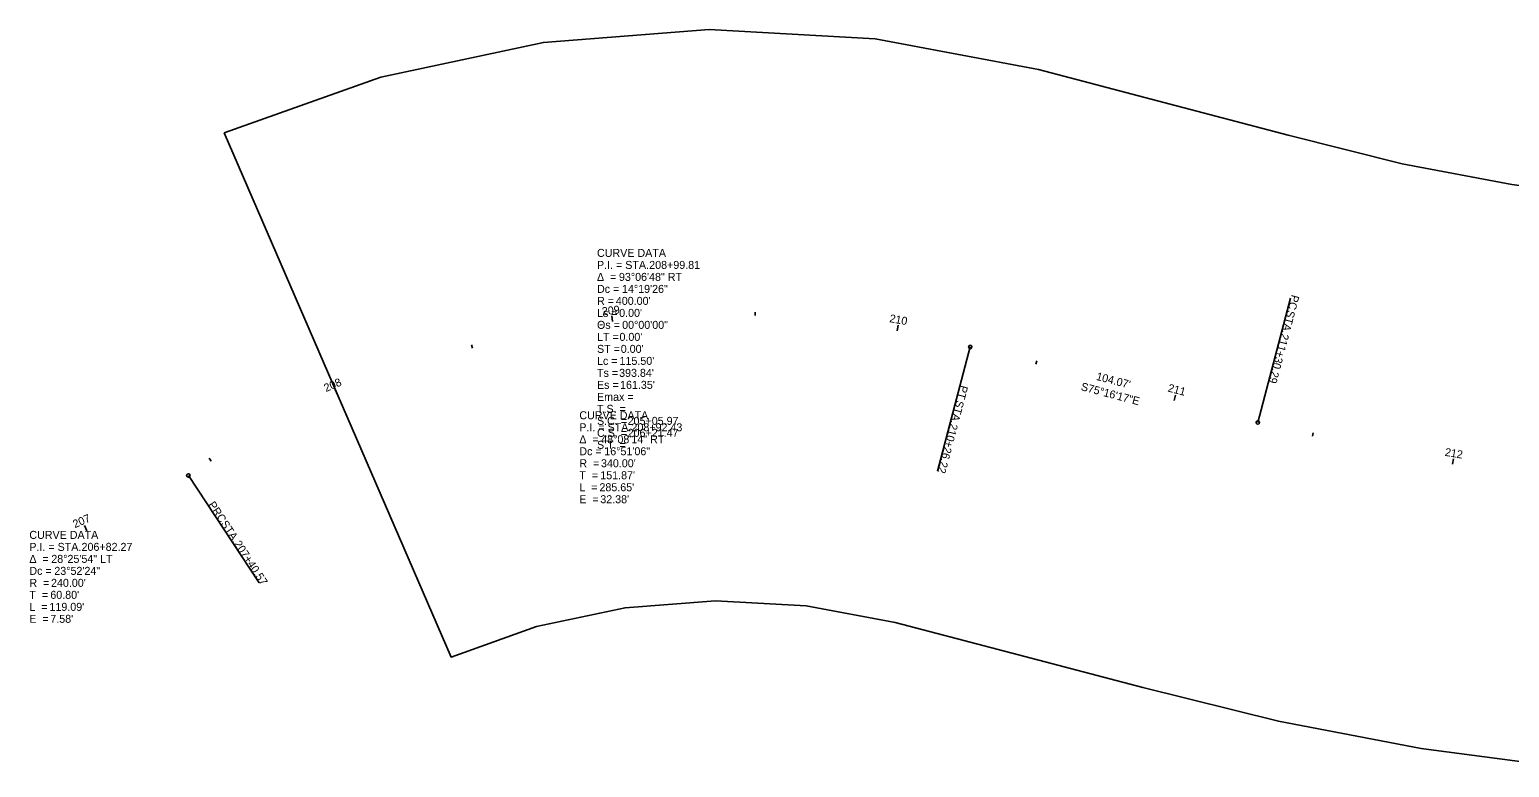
# Model space of a CAD drawing. Extents: x 1600023 to 1602105, y 286460 to 286887.
# Drawn here: x 1601069 to 1601587, y 286628 to 286887 of the extents above; entities that cross this region are included whole.
import ezdxf

# ---------------------------------------------------------------- set-up
doc = ezdxf.new("R2010")
doc.units = 0
for name, color, linetype in [('DT_X_Contour_Minor', 7, 'Continuous'), ('DT_X_Island', 7, 'Continuous'), ('DT_X_Terrain_Boundary', 7, 'Continuous'), ('DT_X_Void', 7, 'Continuous'), ('SC_Scratch3', 7, 'Continuous'), ('UT_X_Overhead_Electric', 7, 'Continuous')]:
    doc.layers.add(name, color=color, linetype=linetype)

msp = doc.modelspace()

# ---------------------------------------------------------------- linework, layer by layer
at = {"layer": 'DT_X_Island'}
for p, q in [((1601498.97, 286749.25), (1601510.41, 286792.77)), ((1601398.32, 286775.71), (1601386.88, 286732.19)), ((1601124.67, 286730.7), (1601149.45, 286693.13))]:
    msp.add_line(p, q, dxfattribs=at)
for centre in [(1601398.32, 286775.71), (1601498.97, 286749.25), (1601124.67, 286730.7)]:
    msp.add_circle(centre, 0.6, dxfattribs=at)
at = {"layer": 'SC_Scratch3'}
for p, q in [((1601273.15, 286784.67), (1601272.92, 286786.65)), ((1601323.06, 286786.69), (1601323.1, 286787.89)), ((1601372.73, 286781.39), (1601373.09, 286783.36)), ((1601224.07, 286775.34), (1601223.76, 286776.5)), ((1601421.32, 286769.66), (1601421.63, 286770.82)), ((1601176.89, 286758.93), (1601176.09, 286760.77)), ((1601469.68, 286756.95), (1601470.19, 286758.88)), ((1601518.1, 286744.48), (1601518.37, 286745.65)), ((1601132.62, 286735.78), (1601131.99, 286736.8)), ((1601567.11, 286734.62), (1601567.44, 286736.6)), ((1601089.09, 286711.32), (1601088.28, 286713.15))]:
    msp.add_line(p, q, dxfattribs=at)
at = {"layer": 'UT_X_Overhead_Electric'}
msp.add_lwpolyline([(1601137.18, 286850.71), (1601216.59, 286667.15), (1601246.49, 286677.8), (1601277.54, 286684.41), (1601309.18, 286686.86), (1601340.88, 286685.12), (1601372.06, 286679.21), (1601415.24, 286667.86), (1601458.76, 286656.42), (1601506.2, 286644.63), (1601556.18, 286635.08), (1601606.63, 286628.49), (1601626.67, 286827.49), (1601587.9, 286832.55), (1601549.49, 286839.88), (1601509.61, 286849.85), (1601466.08, 286861.29), (1601422.21, 286872.82), (1601365.04, 286883.66), (1601306.93, 286886.85), (1601248.92, 286882.35), (1601192, 286870.23)], close=True, dxfattribs=at)

# ---------------------------------------------------------------- texts
at = {"layer": 'DT_X_Contour_Minor'}
msp.add_text("104.07'", height=2.8, rotation=345.2715, dxfattribs=at).set_placement((1601442.2, 286764.22))
at = {"layer": 'DT_X_Island'}
for s, rotation, p in [('PC', 255.2715, (1601510.83, 286794.17)), (' STA. ', 255.2715, (1601509.66, 286789.74)), ('211+30.29', 255.2715, (1601507.26, 286780.6)), ('PT', 255.2715, (1601394.89, 286762.48)), (' STA. ', 255.2715, (1601393.77, 286758.21)), ('210+26.22', 255.2715, (1601391.36, 286749.07)), ('PRC', 303.4087, (1601131.46, 286720.49)), (' STA. ', 303.4087, (1601135.28, 286714.69)), ('207+40.57', 303.4087, (1601140.49, 286706.8))]:
    msp.add_text(s, height=2.8, rotation=rotation, dxfattribs=at).set_placement(p)
at = {"layer": 'DT_X_Terrain_Boundary'}
for s, p in [('CURVE DATA', (1601267.69, 286807.25)), ('P.I. = STA. ', (1601267.69, 286803.05)), ('208+99.81', (1601285.96, 286803.05)), ('Δ  = ', (1601267.69, 286798.85)), ('93°06\'48" RT', (1601275.37, 286798.85)), ('Dc = ', (1601267.69, 286794.65)), ('14°19\'26"', (1601276.43, 286794.65)), ('R = ', (1601267.69, 286790.45)), ("400.00'", (1601274.28, 286790.45)), ('Θs = ', (1601267.69, 286782.05)), ('Ls = ', (1601267.69, 286786.25)), ("0.00'", (1601275.45, 286786.25)), ('00°00\'00"', (1601276.49, 286782.05)), ('LT = ', (1601267.69, 286777.85)), ("0.00'", (1601275.55, 286777.85)), ('ST = ', (1601267.69, 286773.65)), ("0.00'", (1601276, 286773.65)), ('Lc = ', (1601267.69, 286769.45)), ("115.50'", (1601275.57, 286769.45)), ('Ts = ', (1601267.69, 286765.25)), ('Es = ', (1601267.69, 286761.05)), ("393.84'", (1601275.43, 286765.25)), ("161.35'", (1601275.75, 286761.05)), ('Emax = ', (1601267.69, 286756.85)), ('T.S. = ', (1601267.69, 286752.65)), ('CURVE DATA', (1601261.5, 286750.4)), ('P.I. = STA. ', (1601261.5, 286746.2)), ('S.C. = ', (1601267.69, 286748.45)), ('205+05.97', (1601278.41, 286748.45)), ('208+92.43', (1601279.76, 286746.2)), ('Δ  = ', (1601261.5, 286742)), ('C.S. = ', (1601267.69, 286744.25)), ('48°08\'14" RT', (1601269.17, 286742)), ('206+21.47', (1601278.41, 286744.25)), ('Dc = ', (1601261.5, 286737.8)), ('S.T. = ', (1601267.69, 286740.05)), ('16°51\'06"', (1601270.24, 286737.8)), ('R  = ', (1601261.5, 286733.6)), ("340.00'", (1601269.08, 286733.6)), ('T  = ', (1601261.5, 286729.4)), ('L  = ', (1601261.5, 286725.2)), ("285.65'", (1601268.54, 286725.2)), ("151.87'", (1601268.84, 286729.4)), ('E  = ', (1601261.5, 286721)), ("32.38'", (1601268.84, 286721)), ('CURVE DATA', (1601069.01, 286708.52)), ('P.I. = STA. ', (1601069.01, 286704.32)), ('206+82.27', (1601087.28, 286704.32)), ('Δ  = ', (1601069.01, 286700.12)), ('28°25\'54" LT', (1601076.69, 286700.12)), ('Dc = ', (1601069.01, 286695.92)), ('23°52\'24"', (1601077.75, 286695.92)), ('R  = ', (1601069.01, 286691.72)), ("240.00'", (1601076.59, 286691.72)), ('T  = ', (1601069.01, 286687.52)), ('L  = ', (1601069.01, 286683.32)), ("119.09'", (1601076.05, 286683.32)), ("60.80'", (1601076.35, 286687.52)), ('E  = ', (1601069.01, 286679.12)), ("7.58'", (1601076.35, 286679.12))]:
    msp.add_text(s, height=2.8, dxfattribs=at).set_placement(p)
at = {"layer": 'DT_X_Void'}
msp.add_text('S75°16\'17"E', height=2.8, rotation=345.2715, dxfattribs=at).set_placement((1601436.85, 286760.62))
at = {"layer": 'SC_Scratch3'}
for s, rotation, p in [('209', 6.5413, (1601269.57, 286786.77)), ('210', 349.6896, (1601369.89, 286784.45)), ('208', 23.393, (1601172.83, 286759.9)), ('211', 345.2715, (1601467.27, 286760.17)), ('212', 350.4996, (1601564.29, 286737.63)), ('207', 23.7245, (1601084.96, 286712.24))]:
    msp.add_text(s, height=2.8, rotation=rotation, dxfattribs=at).set_placement(p)

doc.saveas('drawing.dxf')
